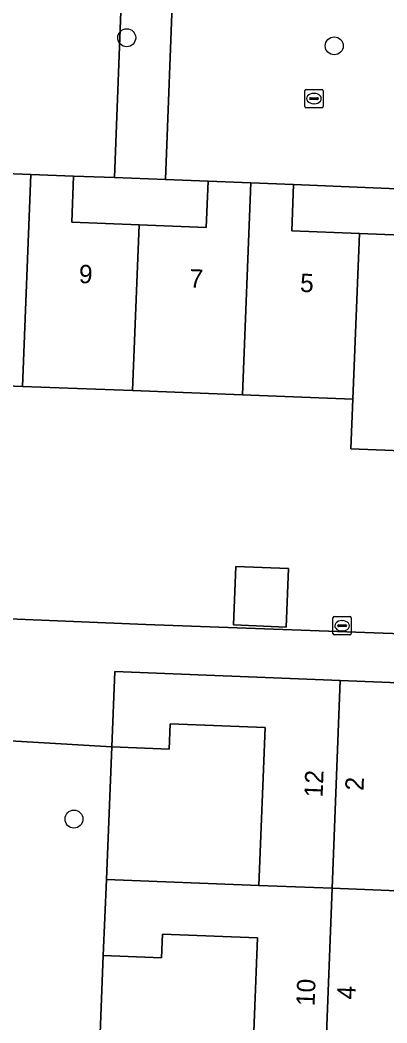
# Model space of a CAD drawing. Extents: x 160786 to 161429, y 386828 to 387485.
# Drawn here: x 161240.6 to 161260.6, y 387264.6 to 387319.3 of the extents above; entities that cross this region are included whole.
import ezdxf

# ---------------------------------------------------------------- set-up
doc = ezdxf.new("R2010")
doc.units = 0
for name, color, linetype in [('IMGEO_Boom', 7, 'Continuous'), ('IMGEO_Erf', 7, 'Continuous'), ('IMGEO_Kolk', 7, 'Continuous'), ('IMGEO_Muur', 7, 'Continuous'), ('IMGEO_Pand', 7, 'Continuous'), ('IMGEO_Pand_nummerreeks', 7, 'Continuous'), ('IMGEO_Rijbaan_lokaal_open', 7, 'Continuous'), ('IMGEO_Voetpad_open', 7, 'Continuous')]:
    doc.layers.add(name, color=color, linetype=linetype)

msp = doc.modelspace()

# ---------------------------------------------------------------- linework, layer by layer
at = {"layer": 'IMGEO_Boom'}
for centre in [(161246.448, 387318.354), (161257.765, 387317.912), (161243.571, 387275.756)]:
    msp.add_circle(centre, 0.489, dxfattribs=at)
at = {"layer": 'IMGEO_Erf'}
for points in [[(161243.546, 387310.812), (161243.448, 387308.301), (161247.12, 387308.157), (161250.788, 387308.014), (161250.887, 387310.54), (161248.555, 387310.625), (161245.787, 387310.728)], [(161255.544, 387310.358), (161255.445, 387307.829), (161259.138, 387307.685), (161262.831, 387307.54), (161262.928, 387310.038)], [(161252.403, 387289.534), (161255.268, 387289.42), (161255.141, 387286.227), (161252.276, 387286.341)], [(161245.337, 387272.46), (161253.647, 387272.13), (161253.99, 387280.747), (161248.821, 387280.952), (161248.766, 387279.565), (161245.64, 387279.689)], [(161244.893, 387261.255), (161253.255, 387260.922), (161253.588, 387269.281), (161248.393, 387269.487), (161248.341, 387268.193), (161245.172, 387268.319)]]:
    msp.add_lwpolyline(points, close=True, dxfattribs=at)
for points in [[(161270.534, 387287.689), (161270.955, 387296.361), (161271.019, 387298.166), (161264.797, 387298.409), (161264.691, 387295.71), (161258.678, 387295.946), (161258.784, 387298.645), (161252.762, 387298.88), (161246.766, 387299.115), (161240.766, 387299.349), (161234.793, 387299.583), (161234.642, 387295.726), (161228.676, 387295.96), (161228.827, 387299.816)], [(161170.163, 387289.466), (161204.081, 387288.161), (161247.486, 387286.367), (161267.914, 387285.628)]]:
    msp.add_lwpolyline(points, dxfattribs=at)
at = {"layer": 'IMGEO_Kolk'}
for p, q in [((161256.159, 387314.614), (161256.159, 387315.466)), ((161256.234, 387315.54), (161257.086, 387315.54)), ((161256.647, 387315.32), (161256.672, 387315.32)), ((161257.16, 387315.466), (161257.16, 387314.614)), ((161256.418, 387315.034), (161256.418, 387315.046)), ((161256.856, 387314.997), (161256.458, 387314.997)), ((161256.461, 387315.083), (161256.859, 387315.083)), ((161256.67, 387314.76), (161256.645, 387314.76)), ((161256.902, 387315.046), (161256.902, 387315.034)), ((161257.086, 387314.54), (161256.234, 387314.54)), ((161257.769, 387286.796), (161258.621, 387286.796)), ((161257.694, 387285.87), (161257.694, 387286.722)), ((161257.953, 387286.29), (161257.953, 387286.302)), ((161258.391, 387286.253), (161257.993, 387286.253)), ((161257.996, 387286.339), (161258.394, 387286.339)), ((161258.182, 387286.576), (161258.207, 387286.576)), ((161258.437, 387286.302), (161258.437, 387286.29)), ((161258.695, 387286.722), (161258.695, 387285.87)), ((161258.621, 387285.796), (161257.769, 387285.796)), ((161258.205, 387286.016), (161258.18, 387286.016))]:
    msp.add_line(p, q, dxfattribs=at)
for points in [[(161256.159, 387314.614), (161256.159, 387315.466)], [(161256.234, 387315.54), (161257.086, 387315.54)], [(161257.16, 387315.466), (161257.16, 387314.614)], [(161257.086, 387314.54), (161256.234, 387314.54)], [(161257.769, 387286.796), (161258.621, 387286.796)], [(161257.694, 387285.87), (161257.694, 387286.722)], [(161258.695, 387286.722), (161258.695, 387285.87)], [(161258.621, 387285.796), (161257.769, 387285.796)]]:
    msp.add_lwpolyline(points, dxfattribs=at)
for centre, radius, start, end in [((161256.236, 387315.464), 0.0765, 91.552, 178.448), ((161256.236, 387315.464), 0.0765, 91.552, 178.448), ((161257.084, 387315.464), 0.0765, 1.552, 88.448), ((161257.084, 387315.464), 0.0765, 1.552, 88.448), ((161256.458, 387315.043), 0.0403, 85.8775, 175.7526), ((161256.455, 387315.033), 0.0366, 178.938, 274.7102), ((161256.859, 387315.04), 0.043, 264.8664, 352.4533), ((161256.863, 387315.045), 0.0386, 1.7309, 96.639), ((161256.236, 387314.616), 0.0765, 181.552, 268.448), ((161256.236, 387314.616), 0.0765, 181.552, 268.448), ((161257.084, 387314.616), 0.0765, 271.552, 358.448), ((161257.084, 387314.616), 0.0765, 271.552, 358.448), ((161257.771, 387286.72), 0.0765, 91.552, 178.448), ((161257.771, 387286.72), 0.0765, 91.552, 178.448), ((161258.619, 387286.72), 0.0765, 1.552, 88.448), ((161258.619, 387286.72), 0.0765, 1.552, 88.448), ((161257.993, 387286.299), 0.0403, 85.8775, 175.7526), ((161257.99, 387286.289), 0.0366, 178.938, 274.7102), ((161258.394, 387286.296), 0.043, 264.8664, 352.4533), ((161258.398, 387286.301), 0.0386, 1.7309, 96.639), ((161257.771, 387285.872), 0.0765, 181.552, 268.448), ((161257.771, 387285.872), 0.0765, 181.552, 268.448), ((161258.619, 387285.872), 0.0765, 271.552, 358.448), ((161258.619, 387285.872), 0.0765, 271.552, 358.448)]:
    msp.add_arc(centre, radius, start, end, dxfattribs=at)
for centre, major_axis, ratio, start_param, end_param in [((161256.646, 387315.04), (-0.387, 0.002), 0.722429, 4.712389, 7.853982), ((161256.671, 387315.04), (-0.39, 0.002), 0.717154, 1.570796, 4.712389), ((161258.181, 387286.296), (-0.387, 0.002), 0.722429, 4.712389, 7.853982), ((161258.206, 387286.296), (-0.39, 0.002), 0.717154, 1.570796, 4.712389)]:
    msp.add_ellipse(centre, major_axis=major_axis, ratio=ratio, start_param=start_param, end_param=end_param, dxfattribs=at)
at = {"layer": 'IMGEO_Muur'}
for points in [[(161245.64, 387279.689), (161245.337, 387272.46)], [(161245.172, 387268.319), (161244.893, 387261.255)]]:
    msp.add_lwpolyline(points, dxfattribs=at)
at = {"layer": 'IMGEO_Pand'}
for points in [[(161238.892, 387310.994), (161238.795, 387308.505), (161235.148, 387308.647), (161234.793, 387299.583), (161240.766, 387299.349), (161241.218, 387310.903)], [(161241.218, 387310.903), (161240.766, 387299.349), (161246.766, 387299.115), (161247.12, 387308.157), (161243.448, 387308.301), (161243.546, 387310.812)], [(161250.887, 387310.54), (161250.788, 387308.014), (161247.12, 387308.157), (161246.766, 387299.115), (161252.762, 387298.88), (161253.215, 387310.449)], [(161253.215, 387310.449), (161252.762, 387298.88), (161258.784, 387298.645), (161259.138, 387307.685), (161255.445, 387307.829), (161255.544, 387310.358)], [(161265.248, 387309.947), (161262.928, 387310.038), (161262.831, 387307.54), (161259.138, 387307.685), (161258.784, 387298.645), (161258.678, 387295.946), (161264.691, 387295.71), (161264.797, 387298.409)], [(161252.276, 387286.341), (161255.141, 387286.227), (161255.268, 387289.42), (161252.403, 387289.534)], [(161245.804, 387283.807), (161245.64, 387279.689), (161248.766, 387279.565), (161248.821, 387280.952), (161253.99, 387280.747), (161253.647, 387272.13), (161257.652, 387271.983), (161258.09, 387283.318)], [(161258.09, 387283.318), (161257.652, 387271.983), (161261.659, 387271.834), (161261.996, 387280.303), (161267.078, 387280.101), (161267.024, 387278.755), (161270.21, 387278.628), (161270.377, 387282.829)], [(161245.172, 387268.319), (161248.341, 387268.193), (161248.393, 387269.487), (161253.588, 387269.281), (161253.255, 387260.922), (161257.217, 387260.735), (161257.652, 387271.983), (161253.647, 387272.13), (161245.337, 387272.46)], [(161261.179, 387260.549), (161261.513, 387268.942), (161266.616, 387268.739), (161266.566, 387267.465), (161269.755, 387267.338), (161269.921, 387271.505), (161261.659, 387271.834), (161257.652, 387271.983), (161257.217, 387260.735)]]:
    msp.add_lwpolyline(points, close=True, dxfattribs=at)
at = {"layer": 'IMGEO_Rijbaan_lokaal_open'}
for points in [[(161202.704, 387312.406), (161205.032, 387312.315), (161207.362, 387312.223), (161214.762, 387311.998), (161217.05, 387311.909), (161219.341, 387311.819), (161226.96, 387311.484), (161229.28, 387311.393), (161231.599, 387311.302), (161238.892, 387310.994), (161241.218, 387310.903), (161243.546, 387310.812), (161245.787, 387310.728), (161246.207, 387321.699)], [(161264.222, 387320.914), (161259.019, 387321.139), (161251.278, 387321.486), (161248.974, 387321.583), (161248.555, 387310.625), (161250.887, 387310.54), (161253.215, 387310.449), (161255.544, 387310.358), (161262.928, 387310.038)]]:
    msp.add_lwpolyline(points, dxfattribs=at)
msp.add_lwpolyline([(161248.555, 387310.625), (161248.974, 387321.583), (161246.382, 387321.692), (161246.207, 387321.699), (161245.787, 387310.728)], close=True, dxfattribs=at)
at = {"layer": 'IMGEO_Voetpad_open'}
for points in [[(161247.486, 387286.367), (161204.081, 387288.161), (161170.163, 387289.466), (161164.829, 387289.6), (161164.69, 387286.821)], [(161138.578, 387288.383), (161137.745, 387283.796), (161143.258, 387283.56), (161169.71, 387282.428), (161181.145, 387282.379), (161181.317, 387282.373), (161201.652, 387281.657), (161201.851, 387281.648), (161211.164, 387281.363), (161211.335, 387281.354), (161231.449, 387280.529), (161245.64, 387279.689), (161245.804, 387283.807), (161258.09, 387283.318), (161270.377, 387282.829), (161270.534, 387287.689)], [(161267.914, 387285.628), (161247.486, 387286.367)], [(161244.893, 387261.255), (161245.172, 387268.319), (161245.337, 387272.46), (161245.64, 387279.689), (161231.449, 387280.529)]]:
    msp.add_lwpolyline(points, dxfattribs=at)

# ---------------------------------------------------------------- texts
at = {"layer": 'IMGEO_Pand_nummerreeks'}
for s, rotation, p in [('9', 357.7066, (161243.823, 387304.984)), ('7', 357.7066, (161249.855, 387304.743)), ('5', 357.7066, (161255.886, 387304.501)), ('12', 87.7903, (161257.128, 387276.921)), ('2', 87.7593, (161259.358, 387277.288)), ('10', 87.7903, (161256.69, 387265.543)), ('4', 87.7593, (161258.913, 387265.906))]:
    msp.add_text(s, height=1, rotation=rotation, dxfattribs=at).set_placement(p)

doc.saveas('drawing.dxf')
